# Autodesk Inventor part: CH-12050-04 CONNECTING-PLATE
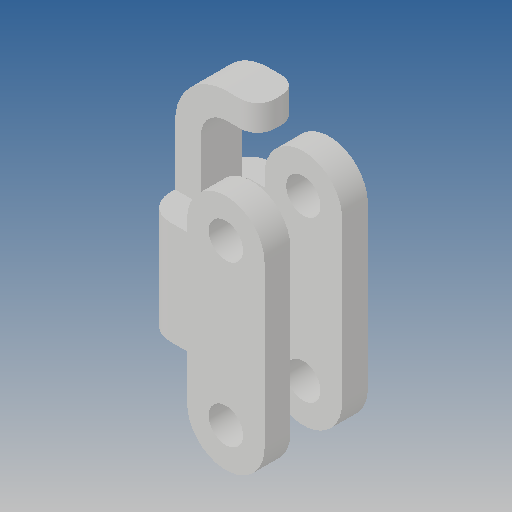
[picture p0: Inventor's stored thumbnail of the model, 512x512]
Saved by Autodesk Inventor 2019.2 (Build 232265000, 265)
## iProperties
Created: 2012-07
Part Number: CH-12050-04 CONNECTING-PLATE
Material: Ogólny
Document SubType Name: Modeling
Designer: CADENGINEERING4
Density: 1 g/cm^3
Appearance: Domyślna
Author: CADENGINEERING4
Revision Number: ÈÎºÎ
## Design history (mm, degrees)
feature "Ô²½Ç2"
node "Bryła1"
